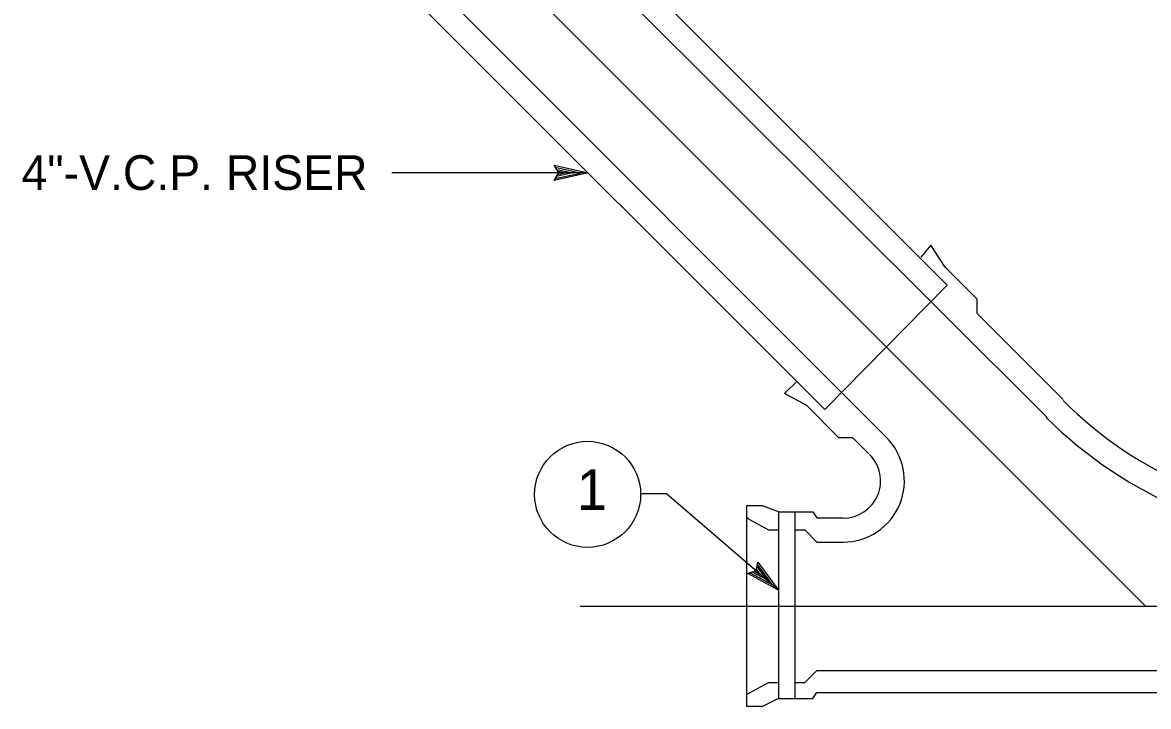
# Model space of a CAD drawing. Extents: x -1680 to 1155, y -802 to 799.
# Drawn here: x 633.2 to 828.2, y -299.3 to -180.9 of the extents above; entities that cross this region are included whole.
import ezdxf

# ---------------------------------------------------------------- set-up
doc = ezdxf.new("R2010")
doc.units = 0
for name, color, linetype in [('G-MARK', 7, 'Continuous'), ('G-TEXT', 7, 'Continuous'), ('Misc CnstDet(22)', 7, 'Continuous')]:
    doc.layers.add(name, color=color, linetype=linetype)

msp = doc.modelspace()

# ---------------------------------------------------------------- linework, layer by layer
at = {"layer": 'G-MARK'}
msp.add_line((731.15, -206.95), (697.13, -206.95), dxfattribs=at)
msp.add_lwpolyline([(764.12, -279.15), (744.68, -262.49), (740.17, -262.49)], dxfattribs=at)
msp.add_circle((731.05, -262.57), 9.18, dxfattribs=at)
at = {"layer": 'G-TEXT'}
for points in [[(725.24, -205.63), (731.15, -206.95), (725.24, -208.26), (725.45, -207.91), (729.78, -206.96), (725.45, -205.98), (725.66, -206.33), (728.43, -206.95), (725.66, -207.56), (725.87, -207.21), (727.07, -206.95), (725.87, -206.68), (726.03, -206.95), (725.24, -208.26), (726.03, -206.95)], [(760.52, -274.29), (764.12, -279.15), (758.8, -276.27), (759.19, -276.15), (763.08, -278.25), (760.45, -274.69), (760.38, -275.09), (762.07, -277.37), (759.57, -276.02), (759.96, -275.89), (761.04, -276.48), (760.31, -275.49), (760.25, -275.8), (758.8, -276.27), (760.25, -275.8)]]:
    msp.add_lwpolyline(points, close=True, dxfattribs=at)
at = {"layer": 'Misc CnstDet(22)'}
for p, q in [((827.64, -281.92), (673.88, -128.16)), ((793.28, -226.39), (708.93, -142.05)), ((810.63, -249.3), (705.12, -144.13)), ((782.86, -252.77), (689.84, -159.75)), ((772.1, -247.91), (687.41, -163.22)), ((772.1, -247.91), (793.28, -226.39)), ((813.41, -246.17), (798.48, -231.25)), ((779.74, -255.55), (776.96, -252.77)), ((758.57, -264.57), (758.57, -299.28)), ((761.34, -264.57), (758.57, -264.57)), ((764.12, -265.61), (761.34, -264.57)), ((758.57, -266.65), (758.92, -266.65)), ((758.57, -266.65), (762.39, -268.73)), ((764.12, -265.61), (764.12, -297.89)), ((764.12, -265.61), (770.02, -265.61)), ((766.9, -265.61), (766.9, -297.89)), ((770.02, -265.61), (770.72, -266.65)), ((770.72, -266.65), (775.23, -266.65)), ((762.39, -268.73), (764.12, -268.73)), ((766.9, -268.73), (768.63, -268.73)), ((768.63, -268.73), (770.72, -270.82)), ((770.72, -270.82), (775.23, -270.82)), ((729.76, -281.92), (950.16, -281.92)), ((768.63, -295.11), (770.72, -293.03)), ((770.72, -293.03), (945.65, -293.03)), ((758.57, -297.2), (762.39, -295.11)), ((762.39, -295.11), (764.12, -295.11)), ((766.9, -295.11), (768.63, -295.11)), ((764.12, -297.89), (761.34, -299.28)), ((764.12, -297.89), (770.02, -297.89)), ((770.02, -297.89), (770.72, -296.85)), ((770.72, -296.85), (902.96, -296.85)), ((761.34, -299.28), (758.57, -299.28))]:
    msp.add_line(p, q, dxfattribs=at)
for points in [[(798.48, -231.25), (798.48, -228.82), (792.93, -223.27), (790.5, -219.45), (788.77, -221.53)], [(776.96, -252.77), (774.53, -252.77), (768.98, -247.22), (765.16, -245.13), (767.25, -243.05)]]:
    msp.add_lwpolyline(points, dxfattribs=at)
for centre, radius, start, end in [((862.53, -197.21), 69.49, 225, 270), ((862.53, -197.21), 73.62, 225, 270), ((775.31, -260.24), 10.59, 270, 45), ((775.31, -260.24), 6.46, 270, 45)]:
    msp.add_arc(centre, radius, start, end, dxfattribs=at)

# ---------------------------------------------------------------- texts
for s, height, p in [('4"-V.C.P. RISER', 6, (633.02, -209.89)), ('1', 7, (729.18, -265.26))]:
    msp.add_text(s, height=height, dxfattribs=at).set_placement(p)

doc.saveas('drawing.dxf')
